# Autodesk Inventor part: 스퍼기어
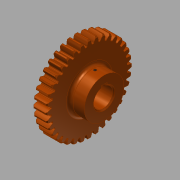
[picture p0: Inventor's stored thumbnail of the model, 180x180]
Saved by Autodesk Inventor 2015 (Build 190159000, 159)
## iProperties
Created: 2019-01
Part Number: 스퍼기어
Material: 알루미늄 6061
Document SubType Name: Modeling
Designer: mduedu
Density: 1 g/cm^3
Appearance: 매끄러움 - 연한 주황색
Author: mduedu
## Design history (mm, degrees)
sketch "스케치1"
  geometry: C1 r 33.5 at (0, 0); 1 further point
  constraints: 1 centre point, 1 coincident
  dimensions: "d0" = 67 diameter of C1
extrude "돌출1" new body sketch "스케치1" stored distance "d2" = 12; taper "d3" = 0 deg
sketch "스케치2" dims "d4" = 72
  geometry: L1 (0, 0)-(-38, 0); L2 (0, 0)-(0, 38); L3 (-0.57, 0)-(-0.57, 37.996); L4 (-1.57, 0)-(-1.57, 37.968); L5 (-2.07, 0)-(-2.07, 37.944); C1 r 33.5 at (0, 0); A1 r 38 centre (0, 0) between (-38, 0) and (0, 38); A2 r 9.246 centre (7.162, 32.926) between (-0.57, 37.996) and (-2.07, 33.436); A3 r 9.246 centre (-7.162, 32.926) between (2.07, 33.436) and (0.57, 37.996); A4 r 33.5 centre (0, 0) between (2.07, 33.436) and (-2.07, 33.436); A5 r 38 centre (0, 0) between (0.57, 37.996) and (-0.57, 37.996); 3 further points
  constraints: 14 point on circle, 10 end point, 6 centre point, 5 coincident, 5 point on line, 3 symmetric about line, 2 parallel, 2 perpendicular, 1 horizontal, 7 other
  dimensions: "d6" = 76 diameter of A1; "d7" = 0.5 distance between parallel lines of L4 L5; "d8" = 1 distance between parallel lines of L3 L4; "d9" = 1.57 distance between parallel lines of L2 L4
extrude "돌출2" join sketch "스케치2" stored distance "d10" = 0; taper "d11" = 0 deg
chamfer "모따기1" distance "d12" = 1; stored, may be unused: second distance "d13" = 2, angle "d14" = 45 deg
fillet "모깎기1" dims "d15" = 0.5
sketch "스케치3"
  geometry: C1 r 17.5 at (0, 0); 1 further point
  constraints: 1 centre point, 1 coincident
  dimensions: "d19" = 35 diameter of C1
extrude "돌출3" join sketch "스케치3" distance "d20" = 13; taper "d21" = 0 deg
sketch "스케치4"
  geometry: L1 (-2.5, 8.124)-(2.5, 8.124); L2 (2.5, 8.124)-(2.5, 10.8); L3 (2.5, 10.8)-(-2.5, 10.8); L4 (-2.5, 10.8)-(-2.5, 8.124); A1 r 8.5 centre (0, 0) between (-2.5, 8.124) and (2.5, 8.124); 1 further point
  constraints: 8 end point, 2 parallel, 2 point on circle, 1 centre point, 1 coincident, 1 horizontal, 1 perpendicular
  dimensions: "d22" = 17 diameter of A1; "d23" = 5 distance of L2.end L3.end; "d24" = 19.3 dimension on A1 L3
extrude "돌출4" cut sketch "스케치4" stored distance "d25" = 13; taper "d26" = 0 deg
sketch "스케치5"
  geometry: C1 r 15 at (0, 0); C2 r 27.5 at (0, 0); 1 further point
  constraints: 2 centre point, 2 coincident
  dimensions: "d33" = 30 diameter of C1; "d34" = 55 diameter of C2
extrude "돌출5" cut sketch "스케치5" distance "d30" = 6; taper "d31" = 0 deg
fillet "모깎기2" dims "d32" = 3
node "작업 평면1"
sketch "스케치6"
  geometry: L1 (17.5, 13)-(-17.5, 13) reference; 2 further points
  constraints: 1 vertical alignment
  dimensions: "d35" = 8 distance from line of point (0, 5) L1
hole "구멍1" sketch "스케치6" at (0, 5) diameter "d36" = 2.459; stored, may be unused: countersink angle "d40" = 90 deg, drill point angle "d42" = 118 deg; dims "d37" = 6, "d38" = 4, "d39" = 2, "d41" = 8
fillet "모깎기3" dims "d43" = 3
chamfer "모따기2" distance "d44" = 1; stored, may be unused: second distance "d45" = 2, angle "d46" = 45 deg
node "솔리드1"
pattern_circular "원형 패턴1" dims "d17" = 360 deg
